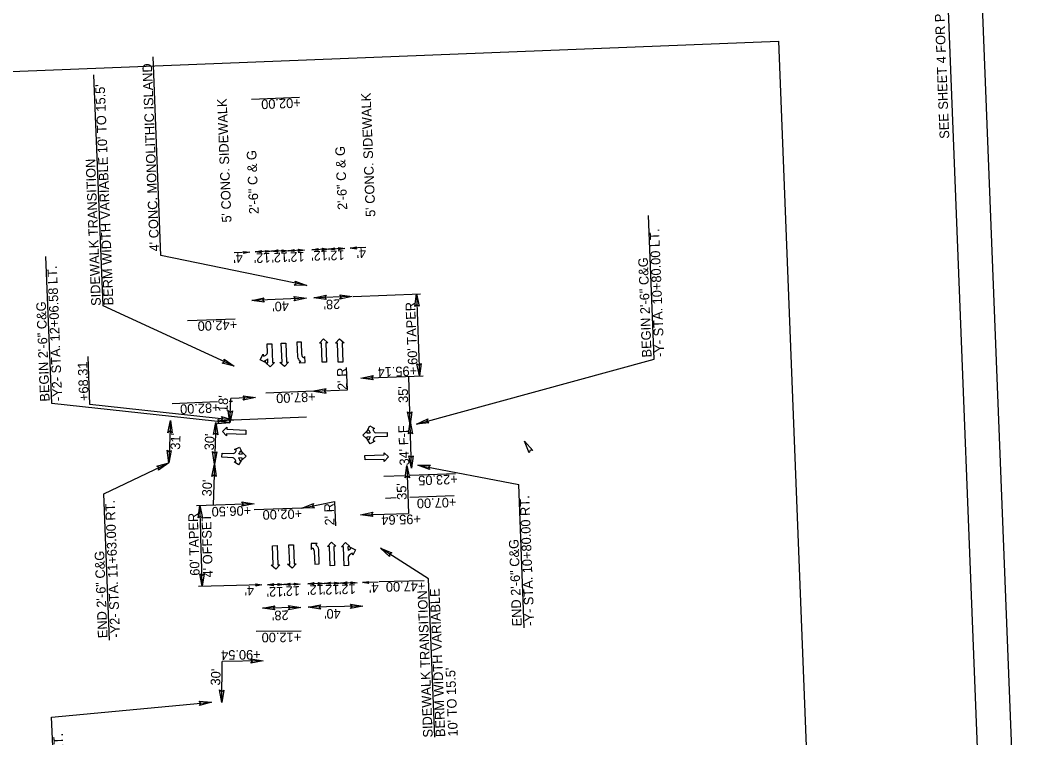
# Model space of a CAD drawing. Extents: x 1627847 to 1629013, y 761524 to 763498.
# Drawn here: x 1628275 to 1629013, y 761909 to 762434 of the extents above; entities that cross this region are included whole.
import ezdxf

# ---------------------------------------------------------------- set-up
doc = ezdxf.new("R2010")
doc.units = 0
for name, color, linetype in [('Default', 7, 'Continuous'), ('Prop Dimension', 7, 'Continuous'), ('Prop Dimension Text', 7, 'Continuous'), ('Prop DSN Text', 7, 'Continuous'), ('Prop Lane Arrow CELL', 7, 'Continuous'), ('Prop Terminator CELL', 7, 'Continuous'), ('Sheet Clip Boundary CELL', 7, 'Continuous'), ('Sheet Plan And Profile CELL', 7, 'Continuous'), ('Sheet Plot Border Outside CELL', 7, 'Continuous')]:
    doc.layers.add(name, color=color, linetype=linetype)

msp = doc.modelspace()

# ---------------------------------------------------------------- linework, layer by layer
at = {"layer": 'Prop Dimension'}
for p, q in [((1628378.07, 762261.82), (1628372.35, 762406.97)), ((1628335.75, 762225.15), (1628329.1, 762393.87)), ((1628479.37, 762377.39), (1628444.4, 762376.01)), ((1628738.7, 762186.18), (1628734.57, 762291.01)), ((1628484.79, 762239.86), (1628378.07, 762261.82)), ((1628443.05, 762264.31), (1628431.56, 762263.86)), ((1628459.04, 762264.94), (1628447.05, 762264.47)), ((1628471.03, 762265.41), (1628459.04, 762264.94)), ((1628483.02, 762265.89), (1628471.03, 762265.41)), ((1628500.5, 762266.58), (1628488.51, 762266.1)), ((1628512.49, 762267.05), (1628500.5, 762266.58)), ((1628527.98, 762267.66), (1628516.49, 762267.21)), ((1628298.26, 762153.78), (1628294.03, 762261.2)), ((1628517.88, 762231.98), (1628489.9, 762230.88)), ((1628518.69, 762231.97), (1628567.79, 762233.9)), ((1628564.86, 762233.79), (1628567.22, 762173.83)), ((1628431.74, 762180.97), (1628335.75, 762225.15)), ((1628484.41, 762230.66), (1628444.44, 762229.09)), ((1628432.43, 762215.41), (1628397.46, 762214.03)), ((1628326.18, 762153.01), (1628324.8, 762188.17)), ((1628564.96, 762138.68), (1628738.7, 762186.18)), ((1628514.49, 762163.6), (1628513.84, 762180.08)), ((1628524.24, 762172.14), (1628569.72, 762173.93)), ((1628560.31, 762138.53), (1628559.22, 762173.52)), ((1628447.23, 762158.21), (1628429.25, 762157.5)), ((1628489.84, 762162.63), (1628454.87, 762161.25)), ((1628489.84, 762162.63), (1628514.49, 762163.6)), ((1628428.54, 762139.52), (1628298.26, 762153.78)), ((1628431.24, 762141.63), (1628326.18, 762153.01)), ((1628419.5, 762154.85), (1628386.37, 762153.55)), ((1628430.41, 762155.29), (1628427.88, 762155.19)), ((1628428.54, 762139.52), (1628429.25, 762157.5)), ((1628484.58, 762143.73), (1628431.24, 762141.63)), ((1628384.99, 762141.3), (1628383.77, 762110.42)), ((1628418.34, 762139.89), (1628417.14, 762109.45)), ((1628336.24, 762087.74), (1628383.77, 762110.42)), ((1628417.14, 762109.45), (1628416.27, 762079.47)), ((1628557.96, 762108.45), (1628559.06, 762073.46)), ((1628565.9, 762108.7), (1628639.64, 762094.5)), ((1628541, 762100.61), (1628555.81, 762101.18)), ((1628560.28, 762101.35), (1628593.55, 762102.64)), ((1628643.77, 761989.68), (1628639.64, 762094.5)), ((1628340.46, 761980.77), (1628336.24, 762087.74)), ((1628550.1, 762084.69), (1628542.38, 762084.41)), ((1628592.48, 762086.18), (1628559.98, 762085.03)), ((1628446.25, 762080.52), (1628404.13, 762079.04)), ((1628481.13, 762077.25), (1628446.16, 762076.06)), ((1628481.14, 762077.25), (1628505.03, 762082.03)), ((1628505.03, 762082.03), (1628505.72, 762064.44)), ((1628524.08, 762072.31), (1628559.06, 762073.46)), ((1628573.78, 762025.63), (1628538.52, 762048.05)), ((1628578.35, 761909.81), (1628573.78, 762025.63)), ((1628451.97, 762021.15), (1628405.46, 762020.1)), ((1628467.96, 762021.51), (1628455.97, 762021.24)), ((1628479.96, 762021.78), (1628467.96, 762021.51)), ((1628497.46, 762022.18), (1628485.46, 762021.91)), ((1628509.45, 762022.45), (1628497.46, 762022.18)), ((1628521.45, 762022.72), (1628509.45, 762022.45)), ((1628536.97, 762023.07), (1628525.45, 762022.81)), ((1628537.73, 762023.6), (1628570.44, 762024.34)), ((1628480.32, 762004.74), (1628452.32, 762004.21)), ((1628525.81, 762005.6), (1628485.81, 762004.84)), ((1628480.61, 761987.35), (1628447.62, 761987.05)), ((1628422.5, 761935.31), (1628422.9, 761965.3)), ((1628422.5, 761935.31), (1628422.9, 761965.3)), ((1628452.9, 761965.63), (1628422.9, 761965.3)), ((1628452.9, 761965.63), (1628422.9, 761965.3)), ((1628298.18, 761924.59), (1628415.12, 761935.4)), ((1628302.45, 761816.24), (1628298.18, 761924.59))]:
    msp.add_line(p, q, dxfattribs=at)
msp.add_arc((1623719.93, 761914.16), 4689.51, 1.29528, 2.01596, dxfattribs=at)
at = {"layer": 'Prop Dimension Text'}
msp.add_line((1628561.32, 762106.55), (1628560.31, 762138.53), dxfattribs=at)
at = {"layer": 'Prop Lane Arrow CELL'}
for p, q in [((1628455.8, 762197.25), (1628459.1, 762197.36)), ((1628456.04, 762190.8), (1628455.8, 762197.25)), ((1628459.1, 762197.36), (1628459.6, 762183.57)), ((1628466.11, 762197.82), (1628469.4, 762197.94)), ((1628466.61, 762183.83), (1628466.11, 762197.82)), ((1628469.4, 762197.94), (1628469.91, 762183.94)), ((1628480.76, 762198.6), (1628477.47, 762198.48)), ((1628477.47, 762198.48), (1628477.85, 762187.93)), ((1628481.09, 762189.45), (1628480.76, 762198.6)), ((1628493.93, 762197.8), (1628496.91, 762201.06)), ((1628495.43, 762197.85), (1628493.93, 762197.8)), ((1628495.93, 762183.86), (1628495.43, 762197.85)), ((1628496.91, 762201.06), (1628500.22, 762198.03)), ((1628500.22, 762198.03), (1628498.72, 762197.97)), ((1628498.72, 762197.97), (1628499.23, 762183.98)), ((1628505.73, 762197.79), (1628508.72, 762201.05)), ((1628507.23, 762197.85), (1628505.73, 762197.79)), ((1628507.73, 762183.86), (1628507.23, 762197.85)), ((1628508.72, 762201.05), (1628512.03, 762198.02)), ((1628512.03, 762198.02), (1628510.53, 762197.97)), ((1628510.53, 762197.97), (1628511.03, 762183.97)), ((1628450.66, 762185.75), (1628452.72, 762189.68)), ((1628452.72, 762189.68), (1628453.17, 762188.29)), ((1628483.34, 762188.08), (1628482.33, 762186.99)), ((1628483.46, 762183.58), (1628483.34, 762188.08)), ((1628454.59, 762183.69), (1628450.66, 762185.75)), ((1628454.14, 762185.13), (1628454.59, 762183.69)), ((1628454.8, 762183.4), (1628456.3, 762183.45)), ((1628458.06, 762180.42), (1628454.8, 762183.4)), ((1628456.3, 762183.45), (1628456.2, 762186.3)), ((1628461.1, 762183.63), (1628458.06, 762180.42)), ((1628459.6, 762183.57), (1628461.1, 762183.63)), ((1628465.11, 762183.77), (1628466.61, 762183.83)), ((1628468.42, 762180.74), (1628465.11, 762183.77)), ((1628471.41, 762184), (1628468.42, 762180.74)), ((1628469.91, 762183.94), (1628471.41, 762184)), ((1628480.07, 762184.56), (1628479.06, 762183.47)), ((1628479.06, 762183.47), (1628483.46, 762183.58)), ((1628499.23, 762183.98), (1628495.93, 762183.86)), ((1628511.03, 762183.97), (1628507.73, 762183.86)), ((1628423.01, 762133.37), (1628426.3, 762136.43)), ((1628426.3, 762136.43), (1628426.23, 762134.94)), ((1628528.86, 762133.77), (1628530.79, 762137.31)), ((1628530.79, 762137.31), (1628534.24, 762135.38)), ((1628426.03, 762130.14), (1628423.01, 762133.37)), ((1628426.09, 762131.64), (1628426.03, 762130.14)), ((1628440.08, 762131.04), (1628426.09, 762131.64)), ((1628426.23, 762134.94), (1628440.22, 762134.34)), ((1628440.22, 762134.34), (1628440.08, 762131.04)), ((1628525.75, 762130.63), (1628528.57, 762133.52)), ((1628528.68, 762127.96), (1628525.75, 762130.63)), ((1628528.57, 762133.52), (1628528.6, 762132.25)), ((1628528.6, 762132.25), (1628531.13, 762132.3)), ((1628531.14, 762129.27), (1628528.65, 762129.23)), ((1628528.65, 762129.23), (1628528.68, 762127.96)), ((1628530.12, 762134.18), (1628528.86, 762133.77)), ((1628534.24, 762135.38), (1628532.98, 762134.97)), ((1628535.13, 762132.37), (1628543.37, 762132.53)), ((1628543.42, 762129.51), (1628535.14, 762129.35)), ((1628543.37, 762132.53), (1628543.42, 762129.51)), ((1628431.97, 762120.07), (1628435.46, 762121.88)), ((1628435.46, 762121.88), (1628437.31, 762118.33)), ((1628531.04, 762124.3), (1628528.98, 762127.72)), ((1628528.98, 762127.72), (1628530.25, 762127.36)), ((1628534.41, 762126.31), (1628531.04, 762124.3)), ((1628533.14, 762126.68), (1628534.41, 762126.31)), ((1628422.65, 762114.42), (1628422.78, 762117.44)), ((1628430.88, 762114.07), (1628422.65, 762114.42)), ((1628422.78, 762117.44), (1628431.06, 762117.08)), ((1628433.22, 762119.63), (1628431.97, 762120.07)), ((1628437.41, 762113.79), (1628434.88, 762113.9)), ((1628435.05, 762116.92), (1628437.54, 762116.81)), ((1628437.31, 762118.33), (1628436.06, 762118.78)), ((1628440.35, 762115.23), (1628437.36, 762112.52)), ((1628437.36, 762112.52), (1628437.41, 762113.79)), ((1628437.54, 762116.81), (1628437.59, 762118.08)), ((1628437.59, 762118.08), (1628440.35, 762115.23)), ((1628527.27, 762115.79), (1628541.27, 762116.19)), ((1628527.37, 762112.49), (1628527.27, 762115.79)), ((1628541.27, 762116.19), (1628541.22, 762117.69)), ((1628541.22, 762117.69), (1628544.46, 762114.68)), ((1628544.46, 762114.68), (1628541.4, 762111.39)), ((1628431.58, 762111.01), (1628432.87, 762111.35)), ((1628434.91, 762108.87), (1628431.58, 762111.01)), ((1628437.05, 762112.29), (1628434.91, 762108.87)), ((1628435.77, 762111.96), (1628437.05, 762112.29)), ((1628541.36, 762112.89), (1628527.37, 762112.49)), ((1628541.4, 762111.39), (1628541.36, 762112.89)), ((1628459.73, 762049.72), (1628463.03, 762049.84)), ((1628460.23, 762035.73), (1628459.73, 762049.72)), ((1628463.03, 762049.84), (1628463.53, 762035.85)), ((1628471.71, 762050.38), (1628475, 762050.5)), ((1628472.21, 762036.39), (1628471.71, 762050.38)), ((1628475, 762050.5), (1628475.51, 762036.51)), ((1628492.27, 762051.53), (1628487.87, 762051.43)), ((1628487.87, 762051.43), (1628487.98, 762046.93)), ((1628487.98, 762046.93), (1628488.99, 762048.01)), ((1628491.26, 762050.45), (1628492.27, 762051.53)), ((1628499.76, 762049.14), (1628502.74, 762052.4)), ((1628501.25, 762049.19), (1628499.76, 762049.14)), ((1628501.76, 762035.2), (1628501.25, 762049.19)), ((1628502.74, 762052.4), (1628506.05, 762049.36)), ((1628506.05, 762049.36), (1628504.55, 762049.31)), ((1628504.55, 762049.31), (1628505.06, 762035.32)), ((1628510.02, 762048.91), (1628513.05, 762052.12)), ((1628511.51, 762048.97), (1628510.02, 762048.91)), ((1628512.01, 762035.18), (1628511.51, 762048.97)), ((1628513.05, 762052.12), (1628516.31, 762049.14)), ((1628516.31, 762049.14), (1628514.81, 762049.08)), ((1628514.81, 762049.08), (1628514.91, 762046.24)), ((1628516.97, 762047.41), (1628516.52, 762048.85)), ((1628516.52, 762048.85), (1628520.45, 762046.79)), ((1628490.23, 762045.56), (1628490.56, 762036.41)), ((1628493.86, 762036.53), (1628493.48, 762047.08)), ((1628515.08, 762041.74), (1628515.31, 762035.29)), ((1628518.39, 762042.86), (1628517.94, 762044.24)), ((1628520.45, 762046.79), (1628518.39, 762042.86)), ((1628458.73, 762035.68), (1628460.23, 762035.73)), ((1628462.04, 762032.64), (1628458.73, 762035.68)), ((1628465.03, 762035.9), (1628462.04, 762032.64)), ((1628463.53, 762035.85), (1628465.03, 762035.9)), ((1628470.71, 762036.34), (1628472.21, 762036.39)), ((1628474.02, 762033.3), (1628470.71, 762036.34)), ((1628477.01, 762036.56), (1628474.02, 762033.3)), ((1628475.51, 762036.51), (1628477.01, 762036.56)), ((1628490.56, 762036.41), (1628493.86, 762036.53)), ((1628505.06, 762035.32), (1628501.76, 762035.2)), ((1628515.31, 762035.29), (1628512.01, 762035.18))]:
    msp.add_line(p, q, dxfattribs=at)
for centre, radius, start, end in [((1628452.12, 762192.6), 4.43, 283.76826, 314.62182), ((1628453.57, 762191.35), 2.52, 311.13173, 347.44373), ((1628482.99, 762188.91), 5.25, 190.73466, 236.04636), ((1628484.35, 762189.56), 3.28, 182.05859, 231.71676), ((1628453.09, 762189.45), 4.43, 283.64945, 314.52805), ((1628534.02, 762135.03), 4, 192.35586, 223.24555), ((1628534.18, 762126.67), 4, 139.33518, 170.11165), ((1628536.88, 762135.86), 4, 192.72505, 223.65519), ((1628537.07, 762125.95), 4, 138.52873, 169.7414), ((1628535.73, 762134.57), 2.28, 220.1651, 254.93113), ((1628535.87, 762127.2), 2.28, 109.02087, 142.01882), ((1628430.15, 762111.91), 2.28, 36.65029, 71.41632), ((1628430.46, 762119.28), 2.28, 285.50606, 318.504), ((1628429.34, 762120.59), 4, 315.01392, 346.22659), ((1628431.82, 762111.34), 4, 8.84105, 39.73074), ((1628432.18, 762119.7), 4, 315.82037, 346.59684), ((1628428.92, 762110.69), 4, 9.21024, 40.14038), ((1628486.98, 762045.45), 3.28, 2.05859, 51.71676), ((1628488.34, 762046.1), 5.25, 10.73466, 56.04636), ((1628518.02, 762043.09), 4.43, 103.64945, 134.52805), ((1628517.54, 762041.19), 2.52, 131.13173, 167.44373), ((1628518.99, 762039.93), 4.43, 103.76826, 134.62182)]:
    msp.add_arc(centre, radius, start, end, dxfattribs=at)
at = {"layer": 'Prop Terminator CELL'}
for points in [[(1628438.52, 762264.91), (1628443.05, 762264.31), (1628438.56, 762263.33), (1628439.1, 762264.15)], [(1628451.57, 762263.87), (1628447.05, 762264.47), (1628451.54, 762265.45), (1628450.99, 762264.62)], [(1628454.51, 762265.54), (1628459.04, 762264.94), (1628454.55, 762263.96), (1628455.09, 762264.78)], [(1628463.56, 762264.34), (1628459.04, 762264.94), (1628463.53, 762265.92), (1628462.98, 762265.1)], [(1628466.5, 762266.01), (1628471.03, 762265.41), (1628466.54, 762264.44), (1628467.08, 762265.26)], [(1628475.55, 762264.82), (1628471.03, 762265.41), (1628475.52, 762266.39), (1628474.97, 762265.57)], [(1628478.49, 762266.48), (1628483.02, 762265.89), (1628478.53, 762264.91), (1628479.07, 762265.73)], [(1628493.04, 762265.51), (1628488.51, 762266.1), (1628493, 762267.08), (1628492.46, 762266.26)], [(1628495.98, 762267.17), (1628500.5, 762266.58), (1628496.01, 762265.6), (1628496.56, 762266.42)], [(1628505.03, 762265.98), (1628500.5, 762266.58), (1628504.99, 762267.55), (1628504.45, 762266.73)], [(1628507.97, 762267.65), (1628512.49, 762267.05), (1628508, 762266.07), (1628508.55, 762266.89)], [(1628521.02, 762266.61), (1628516.49, 762267.21), (1628520.98, 762268.18), (1628520.44, 762267.36)], [(1628476.29, 762243.19), (1628484.79, 762239.86), (1628475.61, 762240.11), (1628477.06, 762241.45)], [(1628475.35, 762231.86), (1628484.41, 762230.66), (1628475.43, 762228.71), (1628476.51, 762230.35)], [(1628498.96, 762229.69), (1628489.9, 762230.88), (1628498.88, 762232.84), (1628497.8, 762231.19)], [(1628508.83, 762233.18), (1628517.88, 762231.98), (1628508.9, 762230.03), (1628509.99, 762231.67)], [(1628563.66, 762224.73), (1628564.86, 762233.79), (1628566.81, 762224.81), (1628565.17, 762225.89)], [(1628453.49, 762227.89), (1628444.44, 762229.09), (1628453.42, 762231.04), (1628452.33, 762229.4)], [(1628424.21, 762186.14), (1628431.74, 762180.97), (1628422.85, 762183.3), (1628424.56, 762184.28)], [(1628568.42, 762182.89), (1628567.22, 762173.83), (1628565.27, 762182.81), (1628566.91, 762181.73)], [(1628533.3, 762170.94), (1628524.24, 762172.14), (1628533.22, 762174.09), (1628532.14, 762172.45)], [(1628438.18, 762159.41), (1628447.23, 762158.21), (1628438.25, 762156.26), (1628439.34, 762157.9)], [(1628498.77, 762164.54), (1628489.84, 762162.63), (1628498.95, 762161.39), (1628497.74, 762162.94)], [(1628422.46, 762144.14), (1628431.24, 762141.63), (1628422.07, 762141.01), (1628423.39, 762142.48)], [(1628430.44, 762148.45), (1628428.54, 762139.52), (1628427.29, 762148.62), (1628428.85, 762147.41)], [(1628561.58, 762147.58), (1628560.31, 762138.53), (1628558.43, 762147.53), (1628560.07, 762146.43)], [(1628383.09, 762132.37), (1628384.99, 762141.3), (1628386.24, 762132.2), (1628384.68, 762133.41)], [(1628416.44, 762130.96), (1628418.34, 762139.89), (1628419.59, 762130.78), (1628418.03, 762132)], [(1628419.76, 762142.04), (1628428.54, 762139.52), (1628419.36, 762138.91), (1628420.68, 762140.38)], [(1628558.98, 762131.49), (1628560.25, 762140.53), (1628562.13, 762131.54), (1628560.5, 762132.64)], [(1628574.05, 762139.56), (1628564.96, 762138.68), (1628573.27, 762142.61), (1628572.58, 762140.76)], [(1628647.41, 762117.75), (1628643.81, 762126.15), (1628650.08, 762119.42), (1628648.11, 762119.52)], [(1628385.68, 762119.35), (1628383.77, 762110.42), (1628382.53, 762119.53), (1628384.09, 762118.31)], [(1628419.04, 762118.38), (1628417.14, 762109.45), (1628415.9, 762118.56), (1628417.45, 762117.35)], [(1628562.58, 762115.59), (1628561.32, 762106.55), (1628559.43, 762115.55), (1628561.07, 762114.45)], [(1628374.98, 762107.94), (1628383.77, 762110.42), (1628376.29, 762105.08), (1628376.64, 762107.02)], [(1628415.33, 762100.5), (1628417.14, 762109.45), (1628418.48, 762100.36), (1628416.91, 762101.56)], [(1628556.69, 762099.4), (1628557.96, 762108.45), (1628559.84, 762099.45), (1628558.21, 762100.55)], [(1628574.45, 762105.47), (1628565.9, 762108.7), (1628575.09, 762108.56), (1628573.66, 762107.2)], [(1628405.3, 762070.07), (1628406.54, 762079.12), (1628408.45, 762070.14), (1628406.81, 762071.23)], [(1628437.2, 762081.75), (1628446.25, 762080.52), (1628437.26, 762078.6), (1628438.36, 762080.24)], [(1628490.26, 762077.5), (1628481.14, 762077.25), (1628489.7, 762080.6), (1628488.88, 762078.8)], [(1628533.12, 762071.06), (1628524.08, 762072.31), (1628533.07, 762074.21), (1628531.97, 762072.57)], [(1628545.29, 762041.92), (1628538.52, 762048.05), (1628547.02, 762044.55), (1628545.19, 762043.81)], [(1628409.59, 762029.2), (1628408.24, 762020.16), (1628406.44, 762029.17), (1628408.06, 762028.06)], [(1628447.45, 762021.82), (1628451.97, 762021.15), (1628447.46, 762020.25), (1628448.02, 762021.06)], [(1628460.48, 762020.57), (1628455.97, 762021.24), (1628460.47, 762022.14), (1628459.92, 762021.33)], [(1628463.45, 762022.19), (1628467.96, 762021.51), (1628463.46, 762020.61), (1628464.02, 762021.42)], [(1628472.48, 762020.84), (1628467.96, 762021.51), (1628472.47, 762022.42), (1628471.91, 762021.6)], [(1628475.44, 762022.46), (1628479.96, 762021.78), (1628475.46, 762020.88), (1628476.01, 762021.7)], [(1628489.98, 762021.24), (1628485.46, 762021.91), (1628489.97, 762022.81), (1628489.41, 762022)], [(1628492.94, 762022.85), (1628497.46, 762022.18), (1628492.95, 762021.28), (1628493.51, 762022.09)], [(1628501.97, 762021.51), (1628497.46, 762022.18), (1628501.96, 762023.08), (1628501.41, 762022.27)], [(1628504.94, 762023.12), (1628509.45, 762022.45), (1628504.95, 762021.55), (1628505.5, 762022.36)], [(1628513.97, 762021.78), (1628509.45, 762022.45), (1628513.96, 762023.35), (1628513.4, 762022.54)], [(1628516.93, 762023.4), (1628521.45, 762022.72), (1628516.94, 762021.82), (1628517.5, 762022.63)], [(1628529.97, 762022.14), (1628525.45, 762022.81), (1628529.96, 762023.72), (1628529.4, 762022.9)], [(1628461.35, 762002.83), (1628452.32, 762004.21), (1628461.34, 762005.98), (1628460.22, 762004.36)], [(1628471.29, 762006.12), (1628480.32, 762004.74), (1628471.3, 762002.97), (1628472.42, 762004.59)], [(1628494.84, 762003.47), (1628485.81, 762004.84), (1628494.83, 762006.62), (1628493.71, 762004.99)], [(1628516.78, 762006.98), (1628525.81, 762005.6), (1628516.79, 762003.83), (1628517.91, 762005.45)], [(1628443.88, 761967.08), (1628452.9, 761965.63), (1628443.87, 761963.93), (1628445, 761965.54)], [(1628443.88, 761967.08), (1628452.9, 761965.63), (1628443.87, 761963.93), (1628445, 761965.54)], [(1628424.17, 761944.28), (1628422.5, 761935.31), (1628421.02, 761944.38), (1628422.61, 761943.2)], [(1628424.17, 761944.28), (1628422.5, 761935.31), (1628421.02, 761944.38), (1628422.61, 761943.2)], [(1628406.01, 761936.12), (1628415.12, 761935.4), (1628406.25, 761932.98), (1628407.25, 761934.68)]]:
    msp.add_lwpolyline(points, close=True, dxfattribs=at)
at = {"layer": 'Sheet Clip Boundary CELL'}
msp.add_lwpolyline([(1628237.36, 761773.38), (1628231.63, 761906.6), (1628210.36, 761904.81), (1628126.56, 761769.01), (1628102.08, 762389.86), (1628829.52, 762418.55), (1628854, 761797.69)], close=True, dxfattribs=at)
at = {"layer": 'Sheet Plan And Profile CELL'}
msp.add_lwpolyline([(1627873.18, 763198.56), (1627932.28, 761699.73), (1628981.47, 761741.1), (1628922.36, 763239.94)], close=True, dxfattribs=at)
at = {"layer": 'Sheet Plot Border Outside CELL'}
msp.add_lwpolyline([(1629013.34, 761567.22), (1628946.36, 763265.9), (1627847.21, 763222.56), (1627914.2, 761523.88)], close=True, dxfattribs=at)

# ---------------------------------------------------------------- texts
at = {"layer": 'Default'}
for s, p in [('SEE SHEET 4 FOR PLAN VIEW', (1628954.47, 762347.3)), ("BERM WIDTH VARIABLE 10' TO 15.5'", (1628343.37, 762225.55)), ('SIDEWALK TRANSITION', (1628334.2, 762225.19)), ('BERM WIDTH VARIABLE', (1628586, 761910.11)), ('SIDEWALK TRANSITION', (1628576.83, 761909.75)), ("10' TO 15.5'", (1628595.17, 761910.47))]:
    msp.add_text(s, height=7, rotation=92.25819, dxfattribs=at).set_placement(p)
at = {"layer": 'Prop Dimension'}
for s, rotation, p in [('+02.00', 182.25819, (1628480.13, 762376.94)), ("60' TAPER", 92.42255, (1628565.74, 762182.1)), ('+42.00', 182.25819, (1628433.66, 762214.86)), ('+68.31', 92.25819, (1628325.32, 762155.65)), ("35'", 91.48242, (1628558.85, 762154.25)), ('+87.00', 182.25819, (1628491.07, 762162.08)), ('+82.00', 182.25819, (1628420.83, 762154.15)), ("60' TAPER", 91.65562, (1628406.38, 762027.96)), ("4' OFFSET", 91.65562, (1628416.04, 762026.73)), ('+02.00', 181.96193, (1628481.17, 762076.7))]:
    msp.add_text(s, height=7, rotation=rotation, dxfattribs=at).set_placement(p)
at = {"layer": 'Prop Dimension Text'}
for s, rotation, p in [('-Y- STA. 10+80.00 LT.', 92.25819, (1628746.04, 762187.86)), ("4'", 182.25819, (1628437.85, 762263.75)), ("12'", 182.25819, (1628458.01, 762263.77)), ("12'", 182.25819, (1628470.9, 762264.16)), ("12'", 182.25819, (1628482.96, 762264.59)), ("12'", 182.25819, (1628500.01, 762265.47)), ("12'", 182.25819, (1628512.22, 762265.76)), ("4'", 182.25819, (1628528, 762267.28)), ('BEGIN 2\'-6" C&G', 92.25819, (1628736.87, 762187.49)), ('-Y2- STA. 12+06.58 LT.', 92.25819, (1628305.9, 762155.6)), ('BEGIN 2\'-6" C&G', 92.25819, (1628296.73, 762155.24)), ("40'", 182.25819, (1628471.51, 762228.44)), ("28'", 182.25819, (1628509.04, 762229.88)), ('+95.14', 181.83292, (1628565.25, 762181.03)), ("2' R", 92.25819, (1628514.36, 762163.78)), ("18'", 87.82454, (1628426.85, 762147.39)), ("34' F-F", 92.05859, (1628559.65, 762108.54)), ("31'", 87.67332, (1628392.02, 762119.83)), ("30'", 87.67332, (1628416.86, 762119.38)), ('+23.05', 182.02199, (1628594.96, 762101.89)), ("30'", 87.67332, (1628415.11, 762085.74)), ("35'", 92.05859, (1628557.81, 762083.45)), ('+07.00', 182.02199, (1628593.95, 762085.08)), ('-Y- STA. 10+80.00 RT.', 92.25819, (1628651.11, 761991.35)), ('-Y2- STA. 11+63.00 RT.', 92.25819, (1628348.23, 761982.73)), ('+06.50', 181.83292, (1628443.91, 762078.98)), ("2' R", 92.25819, (1628505.03, 762064.75)), ('+95.64', 181.83292, (1628568.05, 762072.82)), ('END 2\'-6" C&G', 92.25819, (1628641.94, 761990.99)), ('END 2\'-6" C&G', 92.25819, (1628339.06, 761982.36)), ("4'", 181.29528, (1628446.14, 762020.55)), ("12'", 181.29528, (1628467.5, 762019.73)), ("12'", 181.29528, (1628479.67, 762020.29)), ("12'", 181.29528, (1628497.12, 762021.13)), ("12'", 181.29528, (1628508.56, 762021.24)), ("12'", 181.29528, (1628520.4, 762021.63)), ("4'", 181.29528, (1628537.14, 762022.57)), ('+47.00', 181.30129, (1628571.34, 762023.77)), ("40'", 181.42621, (1628509.48, 762003.67)), ("28'", 181.42621, (1628471.37, 762002.52)), ('+12.00', 180.52053, (1628480.56, 761986.42)), ('+90.54', 180.62338, (1628450.96, 761973.69)), ('+90.54', 180.62338, (1628450.96, 761973.69)), ('+90.54', 180.62338, (1628450.96, 761973.69)), ("30'", 87.67332, (1628421.35, 761947.52)), ("30'", 87.67332, (1628421.35, 761947.52)), ("30'", 87.67332, (1628421.35, 761947.52)), ('-L- STA. 14+60.25 LT.', 92.25819, (1628309.99, 761820.2))]:
    msp.add_text(s, height=7, rotation=rotation, dxfattribs=at).set_placement(p)
at = {"layer": 'Prop DSN Text'}
for s, p in [("4' CONC. MONOLITHIC ISLAND", (1628376.85, 762265.03)), ("5' CONC. SIDEWALK", (1628534.93, 762290.24)), ("5' CONC. SIDEWALK", (1628429.71, 762286.09)), ('2\'-6" C & G', (1628449.6, 762292.29)), ('2\'-6" C & G', (1628514.34, 762295.34))]:
    msp.add_text(s, height=7, rotation=92.25819, dxfattribs=at).set_placement(p)

doc.saveas('drawing.dxf')
